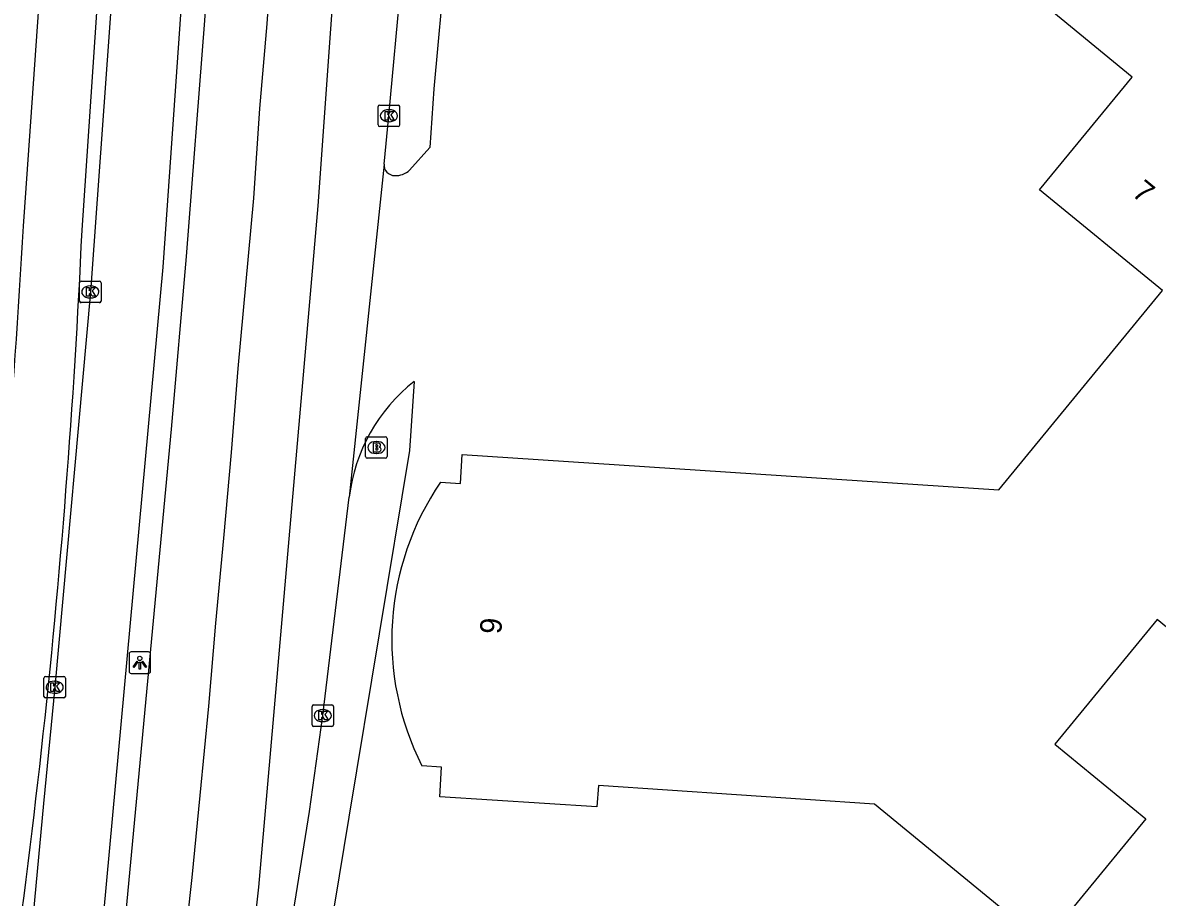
# Model space of a CAD drawing. Extents: x 160158 to 160921, y 381517 to 382041.
# Drawn here: x 160525.6 to 160578.4, y 381802.7 to 381843.4 of the extents above; entities that cross this region are included whole.
import ezdxf

# ---------------------------------------------------------------- set-up
doc = ezdxf.new("R2010")
doc.units = 0
for name, color, linetype in [('IMGEO_Berm_groen', 7, 'Continuous'), ('IMGEO_Brandkraan', 7, 'Continuous'), ('IMGEO_Kolk', 7, 'Continuous'), ('IMGEO_Lichtpunt', 7, 'Continuous'), ('IMGEO_Pand', 7, 'Continuous'), ('IMGEO_Pand_nummerreeks', 7, 'Continuous'), ('IMGEO_Rijbaan_regionaal_gesloten', 7, 'Continuous'), ('IMGEO_Voetpad_open', 7, 'Continuous')]:
    doc.layers.add(name, color=color, linetype=linetype)

msp = doc.modelspace()

# ---------------------------------------------------------------- linework, layer by layer
at = {"layer": 'IMGEO_Berm_groen'}
for points in [[(160528.389, 381833.774), (160534.614, 381926.093), (160532.965, 381928.317)], [(160525.658, 381833.963), (160532.014, 381924.443)]]:
    msp.add_lwpolyline(points, dxfattribs=at)
for centre, radius, start, end in [((160083.837, 381858.802), 442.519, 350.5442, 356.78225), ((160153.748, 381850.796), 375.027, 349.97715, 357.39851)]:
    msp.add_arc(centre, radius, start, end, dxfattribs=at)
at = {"layer": 'IMGEO_Brandkraan'}
for p, q in [((160541.583, 381823.229), (160541.583, 381824.081)), ((160541.658, 381824.155), (160542.51, 381824.155)), ((160542.071, 381823.935), (160542.096, 381823.935)), ((160542.584, 381824.081), (160542.584, 381823.229)), ((160542.094, 381823.375), (160542.069, 381823.375)), ((160542.51, 381823.155), (160541.658, 381823.155))]:
    msp.add_line(p, q, dxfattribs=at)
for points in [[(160541.583, 381823.229), (160541.583, 381824.081)], [(160541.658, 381824.155), (160542.51, 381824.155)], [(160541.931, 381823.855), (160541.931, 381823.455), (160542.144, 381823.455)], [(160542.162, 381823.855), (160541.931, 381823.855)], [(160542.11, 381823.774), (160542.056, 381823.774), (160542.056, 381823.698)], [(160542.056, 381823.698), (160542.109, 381823.698)], [(160542.584, 381824.081), (160542.584, 381823.229)], [(160542.118, 381823.622), (160542.056, 381823.622), (160542.056, 381823.541)], [(160542.056, 381823.541), (160542.118, 381823.541)], [(160542.51, 381823.155), (160541.658, 381823.155)]]:
    msp.add_lwpolyline(points, dxfattribs=at)
for centre, radius, start, end in [((160541.66, 381824.079), 0.0765, 91.552, 178.448), ((160541.66, 381824.079), 0.0765, 91.552, 178.448), ((160542.111, 381823.736), 0.0379, 267.8285, 90.9355), ((160542.166, 381823.71), 0.145, 59.4692, 91.5367), ((160542.191, 381823.757), 0.0922, 285.5137, 58.1501), ((160542.508, 381824.079), 0.0765, 1.552, 88.448), ((160542.508, 381824.079), 0.0765, 1.552, 88.448), ((160541.66, 381823.231), 0.0765, 181.552, 268.448), ((160541.66, 381823.231), 0.0765, 181.552, 268.448), ((160542.119, 381823.581), 0.0404, 269.8759, 90.5077), ((160542.15, 381823.706), 0.251, 268.6676, 293.5347), ((160542.196, 381823.565), 0.105, 301.3115, 78.989), ((160542.508, 381823.231), 0.0765, 271.552, 358.448), ((160542.508, 381823.231), 0.0765, 271.552, 358.448)]:
    msp.add_arc(centre, radius, start, end, dxfattribs=at)
for centre, major_axis, ratio, start_param, end_param in [((160542.07, 381823.655), (-0.387, 0.002), 0.722429, 4.712389, 7.853982), ((160542.095, 381823.655), (-0.39, 0.002), 0.717154, 1.570796, 4.712389)]:
    msp.add_ellipse(centre, major_axis=major_axis, ratio=ratio, start_param=start_param, end_param=end_param, dxfattribs=at)
at = {"layer": 'IMGEO_Kolk'}
for p, q in [((160542.241, 381839.599), (160543.093, 381839.599)), ((160542.166, 381838.673), (160542.166, 381839.525)), ((160542.654, 381839.379), (160542.679, 381839.379)), ((160543.167, 381839.525), (160543.167, 381838.673)), ((160543.093, 381838.599), (160542.241, 381838.599)), ((160542.677, 381838.819), (160542.652, 381838.819)), ((160528.272, 381830.472), (160528.272, 381831.324)), ((160528.347, 381831.398), (160529.199, 381831.398)), ((160528.76, 381831.178), (160528.785, 381831.178)), ((160529.273, 381831.324), (160529.273, 381830.472)), ((160528.783, 381830.618), (160528.758, 381830.618)), ((160529.199, 381830.398), (160528.347, 381830.398)), ((160526.613, 381812.069), (160526.613, 381812.921)), ((160526.688, 381812.995), (160527.54, 381812.995)), ((160527.101, 381812.775), (160527.126, 381812.775)), ((160527.614, 381812.921), (160527.614, 381812.069)), ((160527.124, 381812.215), (160527.099, 381812.215)), ((160527.54, 381811.995), (160526.688, 381811.995)), ((160539.088, 381810.746), (160539.088, 381811.598)), ((160539.163, 381811.672), (160540.015, 381811.672)), ((160540.089, 381811.598), (160540.089, 381810.746)), ((160539.576, 381811.452), (160539.601, 381811.452)), ((160540.015, 381810.672), (160539.163, 381810.672)), ((160539.599, 381810.892), (160539.574, 381810.892))]:
    msp.add_line(p, q, dxfattribs=at)
for points in [[(160542.241, 381839.599), (160543.093, 381839.599)], [(160542.166, 381838.673), (160542.166, 381839.525)], [(160542.487, 381839.299), (160542.61, 381839.299), (160542.61, 381839.148), (160542.74, 381839.299), (160542.904, 381839.299), (160542.758, 381839.148), (160542.911, 381838.899), (160542.759, 381838.899), (160542.674, 381839.063), (160542.61, 381838.996), (160542.61, 381838.899), (160542.487, 381838.899), (160542.487, 381839.299)], [(160543.167, 381839.525), (160543.167, 381838.673)], [(160543.093, 381838.599), (160542.241, 381838.599)], [(160528.272, 381830.472), (160528.272, 381831.324)], [(160528.347, 381831.398), (160529.199, 381831.398)], [(160528.593, 381831.098), (160528.716, 381831.098), (160528.716, 381830.947), (160528.846, 381831.098), (160529.01, 381831.098), (160528.864, 381830.947), (160529.017, 381830.698), (160528.865, 381830.698), (160528.78, 381830.862), (160528.716, 381830.795), (160528.716, 381830.698), (160528.593, 381830.698), (160528.593, 381831.098)], [(160529.273, 381831.324), (160529.273, 381830.472)], [(160529.199, 381830.398), (160528.347, 381830.398)], [(160526.613, 381812.069), (160526.613, 381812.921)], [(160526.688, 381812.995), (160527.54, 381812.995)], [(160526.934, 381812.695), (160527.057, 381812.695), (160527.057, 381812.544), (160527.187, 381812.695), (160527.351, 381812.695), (160527.205, 381812.544), (160527.358, 381812.295), (160527.206, 381812.295), (160527.121, 381812.459), (160527.057, 381812.392), (160527.057, 381812.295), (160526.934, 381812.295), (160526.934, 381812.695)], [(160527.614, 381812.921), (160527.614, 381812.069)], [(160527.54, 381811.995), (160526.688, 381811.995)], [(160539.088, 381810.746), (160539.088, 381811.598)], [(160539.163, 381811.672), (160540.015, 381811.672)], [(160540.089, 381811.598), (160540.089, 381810.746)], [(160539.409, 381811.372), (160539.532, 381811.372), (160539.532, 381811.221), (160539.662, 381811.372), (160539.826, 381811.372), (160539.68, 381811.221), (160539.833, 381810.972), (160539.681, 381810.972), (160539.596, 381811.136), (160539.532, 381811.069), (160539.532, 381810.972), (160539.409, 381810.972), (160539.409, 381811.372)], [(160540.015, 381810.672), (160539.163, 381810.672)]]:
    msp.add_lwpolyline(points, dxfattribs=at)
for centre, start, end in [((160542.243, 381839.523), 91.552, 178.448), ((160542.243, 381839.523), 91.552, 178.448), ((160543.091, 381839.523), 1.552, 88.448), ((160543.091, 381839.523), 1.552, 88.448), ((160542.243, 381838.675), 181.552, 268.448), ((160542.243, 381838.675), 181.552, 268.448), ((160543.091, 381838.675), 271.552, 358.448), ((160543.091, 381838.675), 271.552, 358.448), ((160528.349, 381831.322), 91.552, 178.448), ((160528.349, 381831.322), 91.552, 178.448), ((160529.197, 381831.322), 1.552, 88.448), ((160529.197, 381831.322), 1.552, 88.448), ((160528.349, 381830.474), 181.552, 268.448), ((160528.349, 381830.474), 181.552, 268.448), ((160529.197, 381830.474), 271.552, 358.448), ((160529.197, 381830.474), 271.552, 358.448), ((160526.69, 381812.919), 91.552, 178.448), ((160526.69, 381812.919), 91.552, 178.448), ((160527.538, 381812.919), 1.552, 88.448), ((160527.538, 381812.919), 1.552, 88.448), ((160526.69, 381812.071), 181.552, 268.448), ((160526.69, 381812.071), 181.552, 268.448), ((160527.538, 381812.071), 271.552, 358.448), ((160527.538, 381812.071), 271.552, 358.448), ((160539.165, 381811.596), 91.552, 178.448), ((160539.165, 381811.596), 91.552, 178.448), ((160540.013, 381811.596), 1.552, 88.448), ((160540.013, 381811.596), 1.552, 88.448), ((160539.165, 381810.748), 181.552, 268.448), ((160539.165, 381810.748), 181.552, 268.448), ((160540.013, 381810.748), 271.552, 358.448), ((160540.013, 381810.748), 271.552, 358.448)]:
    msp.add_arc(centre, 0.0765, start, end, dxfattribs=at)
for centre, major_axis, ratio, start_param, end_param in [((160542.653, 381839.099), (-0.387, 0.002), 0.722429, 4.712389, 7.853982), ((160542.678, 381839.099), (-0.39, 0.002), 0.717154, 1.570796, 4.712389), ((160528.759, 381830.898), (-0.387, 0.002), 0.722429, 4.712389, 7.853982), ((160528.784, 381830.898), (-0.39, 0.002), 0.717154, 1.570796, 4.712389), ((160527.1, 381812.495), (-0.387, 0.002), 0.722429, 4.712389, 7.853982), ((160527.125, 381812.495), (-0.39, 0.002), 0.717154, 1.570796, 4.712389), ((160539.575, 381811.172), (-0.387, 0.002), 0.722429, 4.712389, 7.853982), ((160539.6, 381811.172), (-0.39, 0.002), 0.717154, 1.570796, 4.712389)]:
    msp.add_ellipse(centre, major_axis=major_axis, ratio=ratio, start_param=start_param, end_param=end_param, dxfattribs=at)
at = {"layer": 'IMGEO_Lichtpunt'}
for p, q in [((160530.577, 381814.039), (160530.577, 381813.232)), ((160530.577, 381814.039), (160530.577, 381813.232)), ((160531.479, 381814.134), (160530.671, 381814.134)), ((160531.479, 381814.134), (160530.671, 381814.134)), ((160531.573, 381813.232), (160531.573, 381814.039)), ((160531.573, 381813.232), (160531.573, 381814.039)), ((160530.671, 381813.138), (160531.479, 381813.138)), ((160530.671, 381813.138), (160531.479, 381813.138))]:
    msp.add_line(p, q, dxfattribs=at)
for points in [[(160530.951, 381813.703), (160530.99, 381813.675), (160530.802, 381813.413), (160530.764, 381813.44), (160530.951, 381813.703)], [(160531.163, 381813.675), (160531.201, 381813.702), (160531.388, 381813.44), (160531.349, 381813.412), (160531.163, 381813.675)], [(160531.053, 381813.655), (160531.1, 381813.655), (160531.1, 381813.333), (160531.053, 381813.333), (160531.053, 381813.655)]]:
    msp.add_lwpolyline(points, dxfattribs=at)
msp.add_circle((160531.076, 381813.837), 0.0994, dxfattribs=at)
for centre, start, end in [((160530.671, 381814.039), 90, 180), ((160530.671, 381814.039), 90, 180), ((160531.479, 381814.039), 0, 90), ((160531.479, 381814.039), 0, 90), ((160530.671, 381813.232), 180, 270), ((160530.671, 381813.232), 180, 270), ((160531.479, 381813.232), 270, 0), ((160531.479, 381813.232), 270, 360)]:
    msp.add_arc(centre, 0.0946, start, end, dxfattribs=at)
at = {"layer": 'IMGEO_Pand'}
for points in [[(160578.657, 381830.957), (160572.943, 381835.644), (160577.258, 381840.904), (160573.076, 381844.333), (160568.593, 381848.01), (160571.764, 381851.877), (160586.581, 381869.944), (160597.132, 381861.291), (160600.911, 381865.899), (160603.363, 381863.888), (160601.281, 381859.829), (160601.388, 381859.766)], [(160545.068, 381822.034), (160545.997, 381821.984), (160546.076, 381823.333), (160553.382, 381822.841), (160571.054, 381821.687), (160578.657, 381830.957)], [(160587.941, 381807.827), (160578.412, 381815.643), (160573.653, 381809.843), (160577.89, 381806.362), (160574.832, 381802.642), (160573.135, 381800.579), (160565.264, 381807.052), (160552.423, 381807.918), (160552.339, 381806.92), (160545.043, 381807.398), (160545.119, 381808.768), (160544.205, 381808.84)]]:
    msp.add_lwpolyline(points, dxfattribs=at)
msp.add_arc((160555.772, 381814.709), 12.97, 145.6133, 206.9021, dxfattribs=at)
at = {"layer": 'IMGEO_Rijbaan_regionaal_gesloten'}
for points in [[(160550.864, 381933.395), (160546.378, 381915.31), (160545.363, 381910.49), (160544.695, 381906.619), (160543.942, 381898.777), (160543.305, 381890.839), (160542.819, 381882.725), (160542.25, 381874.861), (160541.681, 381866.997), (160541.102, 381859.002), (160540.524, 381851.007), (160539.955, 381843.146), (160539.359, 381834.905), (160538.673, 381827.033), (160537.978, 381819.053), (160537.291, 381811.172), (160536.596, 381803.188), (160535.72, 381795.222), (160534.845, 381787.255), (160534.361, 381783.239), (160534.195, 381779.861)], [(160534.257, 381910.641), (160533, 381891.221), (160531.52, 381869.788), (160530.173, 381850.327), (160528.774, 381830.898), (160527.114, 381812.495), (160526.59, 381807.082), (160525.11, 381791.078), (160524.523, 381784.877), (160523.992, 381779.798)], [(160528.001, 381786.763), (160532.157, 381832.058), (160533.178, 381846.489), (160535.336, 381877.881), (160537.367, 381907.526)], [(160538.181, 381902.406), (160536.45, 381877.717), (160534.083, 381843.54), (160533.226, 381832.551), (160532.528, 381824.512), (160529.545, 381792.616), (160529.18, 381786.609), (160528.742, 381777.62)], [(160542.442, 381836.849), (160542.666, 381839.099), (160543.244, 381845.316), (160543.811, 381853.535), (160543.912, 381855.149)], [(160528.03, 381768.466), (160528.772, 381771.385), (160529.38, 381775.201), (160530.233, 381779.971), (160530.846, 381783.843), (160531.492, 381787.917), (160532.039, 381791.732), (160532.56, 381795.716), (160533.081, 381799.699), (160533.505, 381803.628), (160533.879, 381807.453), (160534.286, 381811.605), (160534.615, 381815.481), (160534.979, 381819.427), (160535.347, 381823.421), (160535.652, 381827.333), (160536.375, 381835.269), (160536.668, 381839.437), (160536.997, 381843.386), (160537.55, 381851.139)], [(160542.442, 381836.849), (160540.822, 381821.339)], [(160534.195, 381779.861), (160536.108, 381789.935), (160537.65, 381798.47), (160538.964, 381806.709), (160539.588, 381811.172), (160540.822, 381821.339)]]:
    msp.add_lwpolyline(points, dxfattribs=at)
at = {"layer": 'IMGEO_Voetpad_open'}
for points in [[(160545.293, 381846.293), (160544.758, 381840.359), (160544.573, 381837.621), (160543.631, 381836.564)], [(160543.837, 381826.73), (160543.619, 381823.508), (160540.802, 381806.439), (160539.434, 381798.152), (160537.466, 381786.23), (160536.414, 381780.659)]]:
    msp.add_lwpolyline(points, dxfattribs=at)
for centre, radius, start, end in [((160542.939, 381836.811), 0.498, 175.6327, 269.1165), ((160542.978, 381837.285), 0.973, 267.256, 312.1967), ((160548.82, 381820.405), 8.053, 128.2306, 173.3358)]:
    msp.add_arc(centre, radius, start, end, dxfattribs=at)

# ---------------------------------------------------------------- texts
at = {"layer": 'IMGEO_Pand_nummerreeks'}
for s, rotation, p in [('7', 320.6391, (160577.188, 381835.421)), ('9', 86.2577, (160547.892, 381814.949))]:
    msp.add_text(s, height=1, rotation=rotation, dxfattribs=at).set_placement(p)

doc.saveas('drawing.dxf')
